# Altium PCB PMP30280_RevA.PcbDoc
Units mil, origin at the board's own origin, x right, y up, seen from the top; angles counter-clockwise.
Board outline 5275 x 1618.75 mil, 2 copper layers (Top Layer, Bottom Layer), stack 62 mil thick; 59 components, 35 nets, 134 pads, 11 vias.
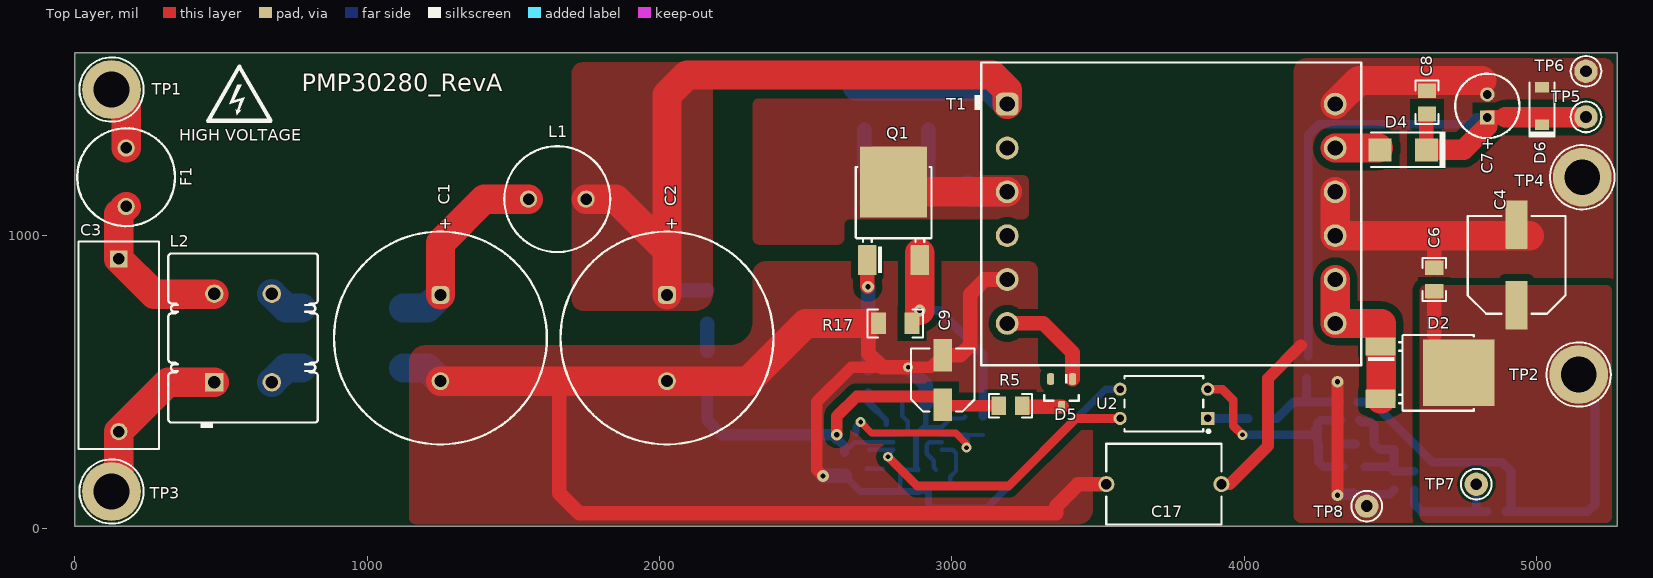
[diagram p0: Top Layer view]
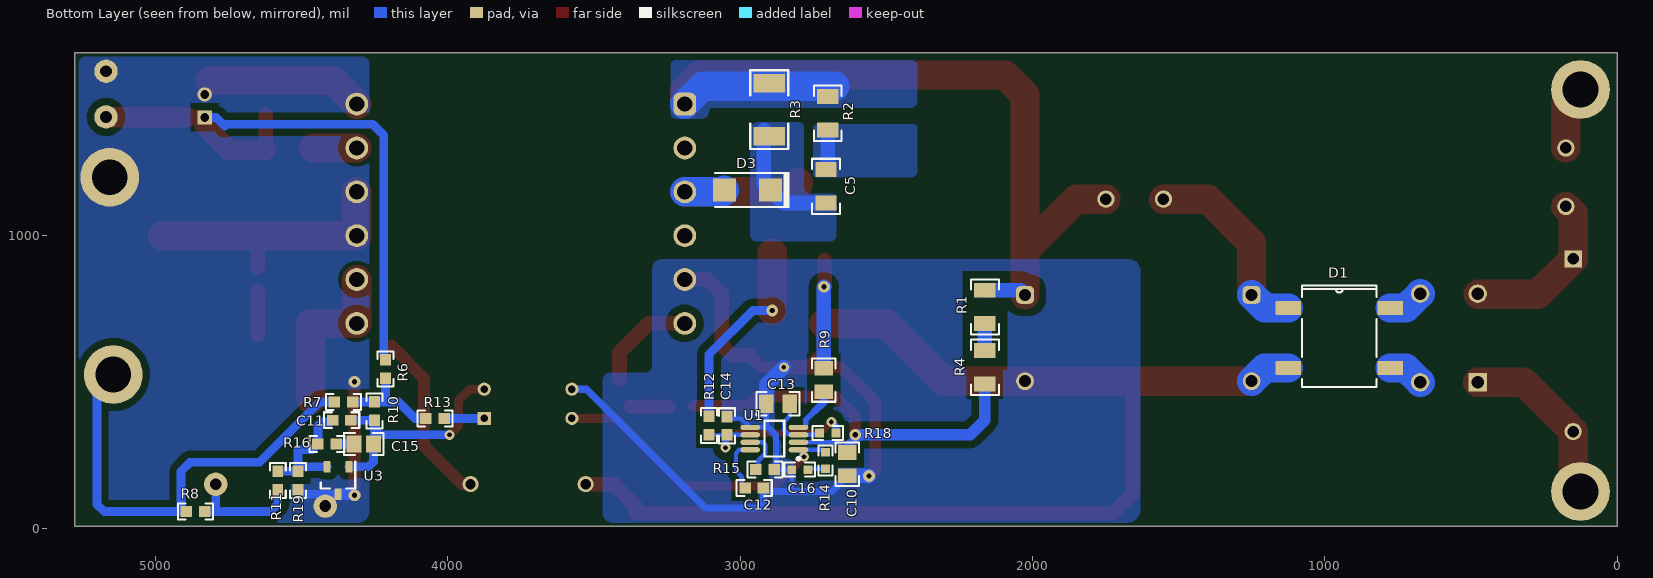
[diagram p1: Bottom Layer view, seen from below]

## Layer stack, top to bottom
Top Solder: solder mask 0.4, Solder Resist, Dk 3.5
Top Layer: signal copper 1.4
Dielectric1: core 59.2, FR-4, Dk 4.8
Bottom Layer: signal copper 1.4
Bottom Solder: solder mask 0.4, Solder Resist, Dk 3.5

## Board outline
0,6.25 5275,6.25 5275,1625 0,1625

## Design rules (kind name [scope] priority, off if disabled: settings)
AcuteAngle [All] p1: minimum=4.50000000000000E+0001 checktracksonly=FALSE
AssemblyTestPointUsage [All] p1: valid=2
Clearance Clearance_PGND_NetR1_1 [InNet('PGND') vs InNet('NetR1_1')] p1: gap=40 ignorepadtopadclearanceinfootprint=FALSE
Clearance Clearance_PGND_NetC2_1 [InNet('PGND') vs InNet('NetC2_1')] p2: gap=40 ignorepadtopadclearanceinfootprint=FALSE
Clearance Clearance_Keepouts [((IsTrack Or IsArc) And Not InPoly) And IsFree and IsKeepOut vs ((IsTrack Or IsArc) And Not InPoly) And IsFree and IsKeepOut] p3: gap=0 ignorepadtopadclearanceinfootprint=FALSE
Clearance Clearance_BoardEdge_MountingHoles [OnCopper and InComponentClass('Mounting Holes') vs IsKeepOut] p4: gap=40 ignorepadtopadclearanceinfootprint=FALSE except(0: Arc-Hole Track-Hole SMDPad-Hole THPad-Hole Via-Hole Fill-Hole Poly-Hole Region-Hole Text-Hole)
Clearance Clearance_BoardEdge_Poly [OnCopper and InPoly vs IsKeepOut] p5: gap=25 ignorepadtopadclearanceinfootprint=FALSE except(0: Arc-Hole Track-Hole SMDPad-Hole THPad-Hole Via-Hole Fill-Hole Poly-Hole Region-Hole Text-Hole)
Clearance Clearance_BoardEdge [OnCopper and Not InComponentClass('Logo') and not InComponentClass('FiducialMark') and not InRegion(1000,500,4000,800) and Not IsKeepout vs IsKeepOut] p6: gap=75 ignorepadtopadclearanceinfootprint=FALSE except(0: Arc-Hole Track-Hole SMDPad-Hole THPad-Hole Via-Hole Fill-Hole Poly-Hole Region-Hole Text-Hole)
Clearance Clearance_Poly [InPolygon] p7: gap=25 ignorepadtopadclearanceinfootprint=FALSE except(0: Arc-Hole Track-Hole SMDPad-Hole THPad-Hole Via-Hole Fill-Hole Poly-Hole Region-Hole Text-Hole)
Clearance [All] p8: gap=7.87 ignorepadtopadclearanceinfootprint=FALSE except(0: Arc-Hole Track-Hole SMDPad-Hole THPad-Hole Via-Hole Fill-Hole Poly-Hole Region-Hole Text-Hole)
ComponentClearance ComponentClearance_MountingHoles_FiducialMarks [InComponentClass('Mounting Holes') vs InComponentClass('FiducialMark')] p1: gap=20 collisioncheckmode=3 verticalgap=10 showdistances=FALSE
ComponentClearance ComponentClearance_Shunt [InComponentClass('Header') vs InComponentClass('Shunt')] p2: gap=0 collisioncheckmode=3 verticalgap=0 showdistances=FALSE
ComponentClearance ComponentClearance_Logo [InComponentClass('Logo')] p3: gap=20 collisioncheckmode=3 verticalgap=10 showdistances=FALSE
ComponentClearance ComponentClearance_ScrewToNut [(HasFootprint('NY PMS 440 0025 PH')) vs (HasFootprint('Keystone_1902C'))] p4: gap=5 collisioncheckmode=3 verticalgap=10 showdistances=FALSE
ComponentClearance ComponentClearance_MountingHoles [InComponentClass('Mounting Holes')] p5: gap=20 collisioncheckmode=3 verticalgap=100000 showdistances=FALSE
ComponentClearance ComponentClearance_SmallPassives [HasFootprint('0201*') or HasFootprint('0402*') or HasFootprint('0508') or HasFootprint('0603*') or HasFootprint('0612') or HasFootprint('0805*') or HasFootprint('0815*') or HasFootprint('0830*') or HasFootprint('1206*') or HasFootprint('1210*') or HasFootprint('1808*') or HasFootprint('1812*') or HasFootprint('1825*') or HasFootprint('2010*') or HasFootprint('2220*') or HasFootprint('2225*') or HasFootprint('2512*') or HasFootprint('2728*') or HasFootprint('3518*') vs HasFootprint('0201*') or HasFootprint('0402*') or HasFootprint('0508') or HasFootprint('0603*') or HasFootprint('0612') or HasFootprint('0805*') or HasFootprint('0815*') or HasFootprint('0830*') or HasFootprint('1206*') or HasFootprint('1210*') or HasFootprint('1808*') or HasFootprint('1812*') or HasFootprint('1825*') or HasFootprint('2010*') or HasFootprint('2220*') or HasFootprint('2225*') or HasFootprint('2512*') or HasFootprint('2728*') or HasFootprint('3518*')] p6: gap=20 collisioncheckmode=3 verticalgap=10 showdistances=FALSE
ComponentClearance ComponentClearance_THtoSMT [IsThruComponent vs IsSMTComponent] p7: gap=20 collisioncheckmode=3 verticalgap=30 showdistances=FALSE
ComponentClearance ComponentClearance_THtoTH [IsThruComponent vs IsThruComponent] p8: gap=20 collisioncheckmode=3 verticalgap=30 showdistances=FALSE
ComponentClearance [All] p9: gap=20 collisioncheckmode=3 verticalgap=10 showdistances=FALSE
DiffPairsRouting [All] p1: maxlimit=100 minlimit=10 mostfreqgap=10 toplayer_minwidth=15 toplayer_maxwidth=15 toplayer_prefwidth=15 bottomlayer_minwidth=15 bottomlayer_maxwidth=15 bottomlayer_prefwidth=15 maxuncoupledlength=1000
FabricationTestPointUsage TestPointUsage [All] p1: valid=2 allowmultiple=FALSE
FabricationTestpoint Testpoint [All] p1: side=3 testpointundercomponent=TRUE minsize=40 maxsize=100 preferedsize=60 minholesize=0 maxholesize=40 preferedholesize=32 testpointgrid=1 allowsidetop=TRUE allowsidebottom=TRUE usegrid=TRUE gridtolerance=0.01
FanoutControl Fanout_LCC [IsLCC] p1: bgadir=Out bgaviamode=Centered fanoutstyle=Auto fanoutdirection=Alternating viagrid=1 // Fanout_LCC (Default Rule)
FanoutControl Fanout_BGA [IsBGA] p2: bgadir=Out bgaviamode=Centered fanoutstyle=Auto fanoutdirection=Alternating viagrid=1 // Fanout_BGA (Default Rule)
FanoutControl Fanout_Default [All] p4: bgadir=Out bgaviamode=Centered fanoutstyle=Auto fanoutdirection=Alternating viagrid=1 // Fanout_Default (Default Rule)
FanoutControl Fanout_Small [(CompPinCount < 5)] p5: bgadir=Out bgaviamode=Centered fanoutstyle=Auto fanoutdirection=OutThenIn viagrid=1 // Fanout_Small (Default Rule)
Height [All] p1: minheight=0 maxheight=1500 prefheight=500
HoleSize [All] p1: absolutevalues=TRUE maxlimit=251 minlimit=8 maxpercent=80.000 minpercent=20.000
MinimumAnnularRing MinimumAnnularRing_ThermalPadVias [IsVia and InAnyComponent] p1: minimumring=5.91
MinimumAnnularRing [All] p2: minimumring=9
MinimumSolderMaskSliver MinimumSolderMaskSliver_Logo [InComponentClass('Logo') vs InComponentClass('Logo')] p1: minsoldermaskwidth=0.7
MinimumSolderMaskSliver [All] p2: minsoldermaskwidth=3.94
PlaneConnect [All] p1: planeconnectstyle=Relief reliefexpansion=10 reliefentries=4 reliefconductorwidth=10 reliefairgap=10
PolygonConnect [All] p1: connectstyle=Direct reliefconductorwidth=10 reliefentries=4 polygonreliefangle="90 Angle" airgapwidth=10
RoutingVias ThermalPadVias [IsVia and InAnyComponent] p1: holewidth=7.87 width=19.68 viastyle="Through Hole" minholewidth=7.87 minwidth=19.68 maxholewidth=12.99 maxwidth=23.62
RoutingVias [All] p2: holewidth=16 width=34 viastyle="Through Hole" minholewidth=7.87 minwidth=26 maxholewidth=40 maxwidth=65
SilkToBoardRegionClearance [Not ((IsComment or IsDesignator) And (Hide <> 'False')) and not InRegion(1000,500,4000,800)] p1:
SilkToSilkClearance SilkToSilkClearance_Pb-FreeLogo [(HasFootprint('Pb-Free_Overlay_Medium') OR HasFootprint('Pb-Free_Overlay_Small')) vs (HasFootprint('Pb-Free_Overlay_Medium') OR HasFootprint('Pb-Free_Overlay_Small'))] p1: silktosilkclearance=0
SilkToSilkClearance [All] p2: silktosilkclearance=0.1
SilkToSolderMaskClearance SilkToComonentPadClearance [IsPad and InAnycomponent] p1: minsilkscreentomaskgap=1 clearancetoexposedcopper=TRUE
SilkToSolderMaskClearance "Silk to Solder Mask Opening" [All] p2: minsilkscreentomaskgap=1 clearancetoexposedcopper=FALSE
SolderMaskExpansion [All] p1: expansion=1.97
Width [All] p1: maxlimit=100 minlimit=6 preferedwidth=10 checkconnectedcopper=TRUE
14 further rules are at their usual default settings.

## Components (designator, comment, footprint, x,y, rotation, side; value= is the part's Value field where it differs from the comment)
C1 "EKXG401ELL101MMN3S" Chemi-Con_1800x3150 1250,650 r270 top value=100uF
C2 "EKXG401ELL101MMN3S" Chemi-Con_1800x3150 2025,650 r270 top value=100uF
C3 "B32922C3224K" B32922_12.5mm 150,625 r270 top value=0.22uF
C4 "875115250001" WCAP-PSHP_800x770 4931.25,900 r90 top value=330uF
C5 "GRM31BR72J152KW01L" 1206 2706.25,1168.75 r270 bottom value=1500pF
C6 "0805ZC105KAT2A" 0805_HV 4650,850 r90 top value=1uF
C7 "EKZN350ELL470ME11D" Chemi-Con_500x1100 4831.25,1443.75 r90 top value=47uF
C8 "GRM21BR71H105KA12L" 0805_HV 4625,1456.25 r90 top value=1uF
C9 "EEE-FC1V6R8R" SM_RADIAL_C 2968.75,506.25 r90 top value=6.8uF
C10 "CC0805KRX7R9BB104" 0805_HV 2632.68,218.45 r270 bottom value=0.1uF
C11 "C0603C681K5RACTU" 0603 4362.5,368.75 r180 bottom value=680pF
C12 "C1608X7R1H473K080AA" 0603 2951.43,137.2 r180 bottom value=0.047uF
C13 "08055C105KAT2A" 0805_HV 2870.18,424.7 r0 bottom value=1uF
C14 "C0603C221K5RACTU" 0603 3045.18,349.7 r90 bottom value=220pF
C15 "Used in BOM report" 0805 4287.5,287.5 r180 bottom value=DNP
C16 "Used in BOM report" 0603_HV 2795.18,199.7 r0 bottom value=DNP
C17 "DE1E3KX222MN4AP01F" KX_1000x700 3725,150 r180 top value=2200pF
D1 "DF04S" DF-S 950,650 r180 bottom value=600V
D2 "MBRD580T4G" DPAK 4600,531.25 r0 top value=60V
D3 "US1J-13-F" SMA 2975,1156.25 r0 bottom value=600V
D4 "SS1200-LTP" SMA 4543.75,1293.75 r180 top value=200V
D5 "BAS21-7-F" SOT-23 3375,462.5 r270 top value=200V
D6 "MMSZ5252B-7-F" SOD-123 5018.75,1443.75 r90 top value=24V
F1 "37211000001" FUSE_372 175,1200 r90 top
"HIGH VOLTAGE" "DANGER HIGH VOLTAGE" IEC_HighVoltage_Small 562.5,1481.25 r0 top (schematic designator "HIGH VOLTAGE1")
L1 "DNP" WE-TI_8075_STU 1650,1125 r0 top value=SHORT
L2 "744822110" WE-CMB_Type_S 575,650 r90 top value=10mH
Q1 "STD9HN65M2" DPAK 2800,1050 r90 top value=650V
R1 "CRCW1206249KFKEA" 1206 2162.5,756.25 r90 bottom value=249k
R2 "CRCW120668R0JNEA" 1206 2700,1418.75 r90 bottom value=68
R3 "CRCW2010100KJNEF" 2010 2900,1431.25 r90 bottom value=100k
R4 "CRCW1206249KFKEA" 1206 2162.5,550 r90 bottom value=249k
R5 "CRCW080510R0FKEA" 0805_HV 3200,418.75 r0 top value=10.0
R6 "CRCW06030000Z0EA" 0603 4212.5,543.75 r90 bottom value=0
R7 "Used in BOM report" 0603 4356.25,431.25 r0 bottom value=DNP
R8 "CRCW060349R9FKEA" 0603 4862.5,56.25 r0 bottom value=49.9
R9 "CRCW08050000Z0EA" 0805_HV 2713.93,505.95 r90 bottom value=0
R10 "Used in BOM report" 0603 4250,400 r90 bottom value=DNP
R11 "CRCW060349K9FKEA" 0603 4581.25,162.5 r270 bottom value=49.9k
R12 "CRCW06031K21FKEA" 0603 3106.25,350.59 r90 bottom value=1.21k
R13 "CRCW06032K00JNEA" 0603 4043.75,375 r0 bottom value=2.0k
R14 "Used in BOM report" 0603_HV 2707.68,230.95 r90 bottom value=DNP
R15 "CRCW060351K1FKEA" 0603 2913.93,199.7 r0 bottom value=51.1k
R16 "Used in BOM report" 0603 4412.5,287.5 r0 bottom value=DNP
R17 "ERJ-8RQFR56V" 1206 2806.25,700 r0 top value=0.56
R18 "Used in BOM report" 0603_HV 2700,325 r0 bottom value=DNP
R19 "CRCW060335K7FKEA" 0603 4512.5,162.5 r90 bottom value=35.7k
T1 "750317021" Wurth_EFD25_6008 3750,1075 r0 top value=2mH
TP1 "Suggest using a net name here" Keystone1503-2 125,1500 r0 top
TP2 "Suggest using a net name here" Keystone1503-2 5143.75,525 r0 top value=Double
TP3 "Suggest using a net name here" Keystone1503-2 125,125 r0 top
TP4 "Suggest using a net name here" Keystone1503-2 5156.25,1200 r0 top value=Double
TP5 "5000" Keystone5000 5168.75,1406.25 r0 top value=Red
TP6 "5001" Keystone5001 5168.75,1562.5 r0 top value=Black
TP7 "5000" Keystone5000 4793.75,150 r90 top value=Red
TP8 "5001" Keystone5001 4418.75,75 r90 top value=Black
U1 "LM5021MM-1/NOPB" MUA08A_N 2882.68,305.95 r0 bottom
U2 "FOD817A" DIP-4 3725,425 r180 top
U3 "ATL431AIDBZR" DBZ0003A_N 4375,162.5 r270 bottom

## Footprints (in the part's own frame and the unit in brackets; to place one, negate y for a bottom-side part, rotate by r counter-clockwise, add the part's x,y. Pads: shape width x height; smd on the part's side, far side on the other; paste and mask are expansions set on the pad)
0603 [mm] "0603 from SM-752 data"
  rect 1x0.95 smd: 1(-0.8,0) 2(0.8,0)
  silkscreen extent -1.52,-0.69 1.52,0.69, body extent -0.87,-0.47 0.87,0.47, height 1
0603_HV [mil] "Ernesto recommended land pattern.  26 mil between pads."
  rect 30x30 smd: 1(-28,0) 2(28,0)
  silkscreen extent -52,-24 52,24, body extent -34,-19 34,19, height 39
0805 [mm] "0805 from SM-752 data"
  rect 1.3x1.5 smd: 1(-0.85,0) 2(0.85,0)
  silkscreen extent -1.72,-0.97 1.72,0.97, body extent -1.1,-0.72 1.1,0.72, height 1.45
0805_HV [mil] "0805 with 30mil clearance between pads"
  rect 50x63 smd: 1(-40,0) 2(40,0)
  silkscreen extent -74,-40 74,40, body extent -43,-29 43,29, height 57
1206 [mm] "1206 from SM-752 data"
  rect 1.3x1.85 smd: 1(-1.45,0) 2(1.45,0)
  silkscreen extent -2.4,-1.21 2.4,1.21, body extent -1.7,-0.9 1.7,0.9, height 1.35
2010 [mm] "Chip Capacitor, Body 5.08x2.54mm, IPC Medium Density"
  rect 1.6x2.7 smd: 1(-2.3,0) 2(2.3,0)
  silkscreen extent -3.42,-1.65 3.42,1.65, body extent -2.73,-1.45 2.73,1.45, height 1.66
B32922_12.5mm [mm] "Epcos film capacitors, 15mm spacing"
  rect 1.5x1.5 hole 1: 1(-7.5,0)
  round 1.5 hole 1: 2(7.5,0)
  silkscreen extent -9,-3.5 9,3.5, body extent -9,-3.5 9,3.5, height 12.5
Chemi-Con_500x1100 [mm] "TH, 2-Leads, Dia 5mm, Lead Sapcing 2mm"
  rect 1.25x1.25 hole 0.75: 1(-1,0)
  round 1.25 hole 0.75: 2(1,0)
  silkscreen extent -2.8,-2.8 2.8,2.8, body extent -2.75,-2.75 2.75,2.75, height 12.5
Chemi-Con_1800x3150 [mm] "TH, 2-Leads, Dia 18mm, Pin Spacing 7.5mm"
  rrect50% 1.55x1.55 hole 1.05: 1(-3.75,0)
  round 1.55 hole 1.05: 2(3.75,0)
  silkscreen extent -9.25,-9.25 9.25,9.25, body extent -9.25,-9.35 9.26,9.15, height 33.01
DBZ0003A_N [mm] "SOT23, 3-Leads, Body 2.9x1.3mm, Pitch 0.95mm, Lead Span 2.4mm, IPC Medium Density"
  rrect17% 1x0.6 smd: 1(-1.2,0.95) 2(-1.2,-0.95) 3(1.2,0)
  silkscreen extent -1.65,-1.5 0.7,1.5, body extent -1.26,-1.46 1.26,1.46, height 0.98
DF-S [mil] "Diodes Inc. recommended land pattern per ap02001.pdf rev 30"
  rect 88x49 smd: 1(-174.5,102.36) 2(-174.5,-102.36) 3(174.5,-102.36) 4(174.5,102.36)
  silkscreen extent -128,-168 128,180, body extent -205,-168 205,168, height 108
DIP-4 [mm] "DIP, 4-Leads, Body 6.86x4.83mm, Pitch 2.54mm"
  rect 1.15x1.15 hole 0.65: 1(-3.81,1.27)
  round 1.15 hole 0.65: 2(-3.81,-1.27) 3(3.81,-1.27) 4(3.81,1.27)
  silkscreen extent -4,-2.41 3.43,2.52, body extent -4.02,-2.41 4.02,2.41, height 5.59
DPAK [mm] "D-PAK, 3-Pads, Body 6.22x6.73mm (max), TO-252AA using nominal STEP model"
  rrect6% 2.6x1.6 smd: 1(-3.4,2.28) 3(-3.4,-2.28)
  rrect2% 6.2x5.8 smd paste-2.9: 4(3.4,0)
  silkscreen extent -4.5,-3.3 4.7,3.28, body extent -3.86,-3.29 5.84,3.29, height 2.48
FUSE_372 [mm] "LITTELFUSE"
  round 1.5 hole 1: 1(-2.54,0) 2(2.54,0)
  silkscreen extent -4.25,-4.25 4.25,4.25, body extent -4.25,-4.25 4.25,4.25, height 8
IEC_HighVoltage_Small [mil]
  silkscreen extent -107,-88 107,97
Keystone1503-2 [mm] "Double Turret"
  round 5.1 hole 3.1: 1(0,0)
  silkscreen extent -2.79,-2.79 2.79,2.79, body extent -2.4,-2.4 2.38,2.4, height 9.22
Keystone5000 [mil] "For Keystone 500x miniature loop terminals"
  round 80 hole 40: 1(0,0)
  silkscreen extent -52,-52 52,52, body extent -49,-49 49,49, height 182
Keystone5001 [mil] "For Keystone 500x miniature loop terminals"
  round 80 hole 40: 1(0,0)
  silkscreen extent -52,-52 52,52, body extent -49,-49 49,49, height 182
KX_1000x700 [mm] "TH, 2-Leads, Dia 10mm, Lead Spacing 10mm"
  round 1.4 hole 0.9: 1(-5,0) 2(5,0)
  silkscreen extent -5,-3.5 5,3.5, body extent -5.32,-3.5 5.33,3.5, height 12.99
MUA08A_N [mm] "TSOP, 8-Leads, Body 3x3mm, Pitch 0.65mm, IPC Medium Density"
  oval 1.7x0.45 smd: 1(-2.1,0.975) 2(-2.1,0.325) 3(-2.1,-0.325) 4(-2.1,-0.975) 5(2.1,-0.975) 6(2.1,-0.325) 7(2.1,0.325) 8(2.1,0.975)
  silkscreen extent -2.22,-1.55 0.85,1.87, body extent -1.6,-1.6 1.6,1.6, height 1.09
SM_RADIAL_C [mm] "5 x 5.8mm:  Panasonic C"
  rect 2.8x1.6 smd: 1(-2.15,0) 2(2.15,0)
  silkscreen extent -2.75,-2.75 2.75,2.75, body extent -2.75,-2.75 2.75,2.75, height 6.1
SMA [mm] "Molded Diode, 2-Leads, Body 4.3x2.6mm, IPC Medium Density, based on OnSemi component dimensions and land pattern"
  rect 2x2 smd: 1(-2,0) 2(2,0)
  silkscreen extent -3.66,-1.57 2.79,1.57, body extent -2.6,-1.3 2.6,1.3, height 2.42
SOD-123 [mm] "On Semi recommended land pattern"
  rect 0.915x1.22 smd: 1(-1.637,0) 2(1.637,0)
  silkscreen extent -2.74,-1.17 2.03,1.17, body extent -1.93,-0.9 1.93,0.9, height 1.35
SOT-23 [mm] "SOT23, 3-Leads, Body 2.9x1.3mm, Pitch 0.95mm, Lead Span 2.5mm, IPC Medium Density"
  rrect50% 1x0.6 smd: 1(-1.2,0.95) 2(-1.2,-0.95) 3(1.2,0)
  silkscreen extent -1.63,-1.5 0.7,1.5, body extent -1.16,-1.45 1.21,1.45, height 1
WCAP-PSHP_800x770 [mm] "SMD, 2-Leads, Body 8.3x8.3mm"
  rrect5% 4.2x1.9 smd: 1(-3.5,0) 2(3.5,0)
  silkscreen extent -4.25,-4.25 4.25,4.25, body extent -4.5,-4.15 4.5,4.15, height 7.67
WE-CMB_Type_S [mm] "TH, 4-Leads, Body 14.7x13mm"
  rect 1.6x1.6 hole 1.1: 1(-3.85,2.5)
  round 1.6 hole 1.1: 2(-3.85,-2.5) 3(3.85,-2.5) 4(3.85,2.5)
  silkscreen extent -7.8,-6.5 7.35,6.5, body extent -7.77,-6.5 7.77,6.5, height 20
WE-TI_8075_STU [mm] "TH, 2-Leads, Dia 9.5mm, Pin Spacing 5mm"
  round 1.5 hole 1: 1(-2.5,0) 2(2.5,0)
  silkscreen extent -4.6,-4.6 4.6,4.6, body extent -5.8,-5.8 5.8,5.8, height 9.7
Wurth_EFD25_6008 [mm] "TH, 12-Leads, Body 33x26.3mm"
  rrect50% 1.98x1.98 hole 1.32: 1(-14.25,9.525)
  round 1.98 hole 1.32: 2(-14.25,5.715) 3(-14.25,1.905) 4(-14.25,-1.905) 5(-14.25,-5.715) 6(-14.25,-9.525) 7(14.25,-9.525) 8(14.25,-5.715) 9(14.25,-1.905) 10(14.25,1.905) 11(14.25,5.715) 12(14.25,9.525)
  silkscreen extent -17.1,-13.15 16.5,13.15, body extent -16.01,-12.98 16,12.99, height 13.95

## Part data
C1 C2: library part CMP-0074694-1, "CAP, AL, 100 µF, 400 V, +/- 20%, TH", Cap_Case=18x31.5, Manufacturer=Chemi-Con, Supplier Part Number 1=565-1469-ND, Tolerance_%=20%, Value2=400V, ValueDisplayed=100µF
C3: "CAP, Film, 0.22 µF, 630 V,+/- 10%, TH", Manufacturer=TDK, Supplier Part Number 1=495-6907-ND, Tolerance_%=10, Value2=630V, ValueDisplayed=0.22µF
C4: library part CMP-0001609-3, "CAP, Aluminum Polymer, 330 µF, 10 V,+/- 20%, 0.02 ohm, D8xL7.7mm SMD", Cap_Case=8X7.7mm, Manufacturer="Wurth Elektronik", Supplier Part Number 1=732-6449-1-ND, Tolerance_%=20%, Value1="0.02 ohm", Value2=10V, ValueDisplayed=330µF
C5: "CAP, CERM, 1500 pF, 630 V,+/- 10%, X7R, 1206", Cap_Case=1206, Manufacturer=MuRata, Supplier Part Number 1=490-3507-1-ND, TempCo=X7R, Tolerance_%=10, Value2=630V, ValueDisplayed=1500pF
C6: "CAP, CERM, 1 µF, 10 V,+/- 10%, X7R, 0805", Cap_Case=0805, Manufacturer=AVX, Supplier Part Number 1=478-1405-1-ND, TempCo=X7R, Tolerance_%=10, Value1="0.008 ohm", Value2=10V, ValueDisplayed=1µF
C7: library part CMP-0074695-1, "CAP, AL, 47 µF, 35 V, +/- 20%, 0.38 ohm, TH", Cap_Case=5x11, Manufacturer=Chemi-Con, Supplier Part Number 1=565-4239-ND, Tolerance_%=20%, Value1="0.38 ohm", Value2=35V, ValueDisplayed=47µF
C8: "CAP, CERM, 1 µF, 50 V,+/- 10%, X7R, 0805", Cap_Case=0805, Manufacturer=MuRata, Supplier Part Number 1=490-4736-1-ND, TempCo=X7R, Tolerance_%=10, Value1=Unknown, Value2=50V, ValueDisplayed=1µF
C9: "CAP, AL, 6.8 µF, 35 V, +/- 20%, 1.8 ohm, SMD", Cap_Case=C, Manufacturer=Panasonic, Supplier Part Number 1=PCE4033CT-ND, Tolerance_%=20, Value1="1.8 ohm", Value2=35V, ValueDisplayed=6.8µF
C10: "CAP, CERM, 0.1 µF, 50 V,+/- 10%, X7R, 0805", Cap_Case=0805, Manufacturer="Yageo America", Supplier Part Number 1=311-1140-1-ND, TempCo=X7R, Tolerance_%=10, Value2=50V, ValueDisplayed=0.1µF
C11: "CAP, CERM, 680 pF, 50 V, +/- 10%, X7R, 0603", Cap_Case=0603, Manufacturer=Kemet, Supplier Part Number 1=399-1077-1-ND, TempCo=X7R, Tolerance_%=10, Value1=Unknown, Value2=50V, ValueDisplayed=680pF
C12: "CAP, CERM, 0.047 µF, 50 V,+/- 10%, X7R, 0603", Cap_Case=0603, Manufacturer=TDK, Supplier Part Number 1=445-1313-1-ND, TempCo=X7R, Tolerance_%=10, Value1="0.049007 ohm", Value2=50V, ValueDisplayed=0.047µF
C13: "CAP, CERM, 1 µF, 50 V, +/- 10%, X7R, 0805", Cap_Case=0805, Manufacturer=AVX, Supplier Part Number 1=478-7956-1-ND, TempCo=X7R, Tolerance_%=10, Value1=Unknown, Value2=50V, ValueDisplayed=1µF
C14: "CAP, CERM, 220 pF, 50 V,+/- 10%, X7R, 0603", Cap_Case=0603, Manufacturer=Kemet, Supplier Part Number 1=399-1071-1-ND, TempCo=X7R, Tolerance_%=10, Value1=Unknown, Value2=50V, ValueDisplayed=220pF
C15 C16: library part Capacitor, "CAP, CERM, xxxF, xxV, [TempCo], xx%, [PackageReference]", Alternate Manufacturer=-
C17: library part DE1E3KX332MN4AP01F, "CAP, CERM, 2200 pF, 300 V, +/- 20%, E, D10xT7mm", Cap_Case=10x7mm, Manufacturer=MuRata, Supplier Part Number 1=490-9516-1-ND, TempCo=E, Tolerance_%=20, Value1=Unknown, Value2=300V, ValueDisplayed=2200pF
D1: library part DF06S-E3, "Diode, Switching-Bridge, 400 V, 1.5A,", Current - Reverse Leakage @ Vr="5µA @ 400V", Manufacturer=Vishay-Semiconductor, Operating Temperature="-55°C ~ 150°C (TJ)", Supplier Device Package=4-SDIP, Supplier Part Number 1=DF04S-E3/45GI-ND, Value1=1A, Value2=1.1V, Voltage - Peak Reverse (Max)=400V
D2: library part MBRD360T4G, "Diode, Schottky, 80 V, DPAK", Capacitance @ Vr, F="300pF @ 5V, 1MHz", Current - Reverse Leakage @ Vr="1mA @ 80V", Manufacturer="SMC Diode Solutions", Operating Temperature - Junction="-55°C ~ 150°C", Supplier Device Package=DPAK, Supplier Part Number 1=MBRD580, Value1=3A, Value2=0.6V
D3: "Diode, Ultrafast, 600 V, 1 A, SMA", Manufacturer="Diodes Inc.", Supplier Part Number 1=US1J-FDICT-ND, Value1=1A, Value2=1.7V
D4: "Diode, Schottky, 200 V, 1 A, SMA", Manufacturer="Micro Commercial Components", Supplier Part Number 1=SS1200-LTPMSCT-ND, Value1=1A, Value2=0.92V
D5: "Diode, Switching, 200 V, 0.2 A, SOT-23", Manufacturer="Diodes Inc.", Supplier Part Number 1=BAS21-FDICT-ND, Value1=0.2A, Value2=1.25V
D6: "Diode, Zener, 24 V, 500 mW, SOD-123", Manufacturer="Diodes Inc.", Power_W=0.5, Supplier Part Number 1=MMSZ5252B-FDICT-ND, Value1=0.5W
F1: "Fuse, 1 A, 250VAC/VDC, TH", Irating_A=1, Manufacturer=Littelfuse, Supplier Part Number 1=WK4248CT-ND
"HIGH VOLTAGE": library part IEC_HighVoltage, "IEC 61010-1 High Voltage Warning"
L1: library part 744732681, "Inductor, Unshielded Drum Core, Metal Composite, 680 µH, 0.42 A, 2.2 ohm, TH", Manufacturer="Wurth Elektronik", Supplier Part Number 1=732-3753-ND, Value1="2.2 ohm", Value2=0.42A, ValueDisplayed=SHORT
L2: "Coupled inductor, 10 mH, 1 A, 0.36 ohm, TH", Manufacturer="Wurth Elektronik", Supplier Part Number 1=732-1442-ND, ValueDisplayed=10mH
Q1: library part CMP-0001614-1, "MOSFET, N-CH, 650 V, 5.5 A, DPAK", Alternate Manufacturer=None, Manufacturer=STMicroelectronics, Supplier Part Number 1=497-16036-1-ND, Value1="? ohm", Value2="11.5 nC"
R1 R4: "RES, 249 k, 1%, 0.25 W, 1206", Manufacturer=Vishay-Dale, Power_W=0.25, Supplier Part Number 1=541-249KFCT-ND, TempCo="100 ppm/C", Tolerance_%=1, Value1=1%, Value2=0.25W, Value_Code=249k
R2: "RES, 68, 5%, 0.25 W, 1206", Manufacturer=Vishay-Dale, Power_W=0.25, Supplier Part Number 1=541-68ECT-ND, TempCo="200 ppm/C", Tolerance_%=5, Value1=5%, Value2=0.25W, Value_Code=68R0, ValueDisplayed=68
R3: "RES, 100 k, 5%, 0.75 W, AEC-Q200 Grade 0, 2010", Manufacturer=Vishay-Dale, Power_W=0.75, Supplier Part Number 1=541-100KWCT-ND, TempCo="200 ppm/C", Tolerance_%=5, Value1=5%, Value2=0.75W, Value_Code=100k
R5: "RES, 10.0, 1%, 0.125 W, 0805", Manufacturer=Vishay-Dale, Power_W=0.125, Supplier Part Number 1=541-10.0CCT-ND, TempCo="100 ppm/C", Tolerance_%=1, Value1=1%, Value2=0.125W, Value_Code=10R0, ValueDisplayed=10.0
R6: "RES, 0, 5%, 0.1 W, 0603", Manufacturer=Vishay-Dale, Power_W=0.1, Supplier Part Number 1=541-0.0GCT-ND, TempCo="200 ppm/C", Tolerance_%=5, Value1=5%, Value2=0.1W, Value_Code=0000, ValueDisplayed=0
R7 R10 R14 R16 R18: library part Resistor, "RES, xxx ohm, x%, xW, [PackageReference]", Alternate Manufacturer=-
R8: "RES, 49.9, 1%, 0.1 W, 0603", Manufacturer=Vishay-Dale, Power_W=0.1, Supplier Part Number 1=541-49.9HCT-ND, TempCo="100 ppm/C", Tolerance_%=1, Value1=1%, Value2=0.1W, Value_Code=49R9, ValueDisplayed=49.9
R9: "RES, 0, 5%, 0.125 W, 0805", Manufacturer=Vishay-Dale, Power_W=0.125, Supplier Part Number 1=541-0.0ACT-ND, TempCo="200 ppm/C", Tolerance_%=5, Value1=5%, Value2=0.125W, Value_Code=0000, ValueDisplayed=0
R11: "RES, 49.9 k, 1%, 0.1 W, 0603", Manufacturer=Vishay-Dale, Power_W=0.1, Supplier Part Number 1=541-49.9KHCT-ND, TempCo="100 ppm/C", Tolerance_%=1, Value1=1%, Value2=0.1W, Value_Code=49k9, ValueDisplayed=49.9k
R12: "RES, 1.21 k, 1%, 0.1 W, 0603", Manufacturer=Vishay-Dale, Power_W=0.1, Supplier Part Number 1=541-1.21KHCT-ND, TempCo="100 ppm/C", Tolerance_%=1, Value1=1%, Value2=0.1W, Value_Code=1k21, ValueDisplayed=1.21k
R13: "RES, 2.0 k, 5%, 0.1 W, 0603", Manufacturer=Vishay-Dale, Power_W=0.1, Supplier Part Number 1=541-2.0KGCT-ND, TempCo="200 ppm/C", Tolerance_%=5, Value1=5%, Value2=0.1W, Value_Code=2k00, ValueDisplayed=2.0k
R15: "RES, 51.1 k, 1%, 0.1 W, 0603", Manufacturer=Vishay-Dale, Power_W=0.1, Supplier Part Number 1=541-51.1KHCT-ND, TempCo="100 ppm/C", Tolerance_%=1, Value1=1%, Value2=0.1W, Value_Code=51k1, ValueDisplayed=51.1k
R17: "RES, 0.56, 1%, 0.25 W, 1206", Manufacturer=Panasonic, Power_W=0.25, Supplier Part Number 1=P.56RCT-ND, TempCo="250 ppm/C", Tolerance_%=1, Value1=1%, Value2=0.25W, Value_Code=R560, ValueDisplayed=0.56
R19: "RES, 35.7 k, 1%, 0.1 W, 0603", Manufacturer=Vishay-Dale, Power_W=0.1, Supplier Part Number 1=541-35.7KHCT-ND, TempCo="100 ppm/C", Tolerance_%=1, Value1=1%, Value2=0.1W, Value_Code=35k7, ValueDisplayed=35.7k
T1: library part CMP-0077154-2, "Transformer, 2000 uH, TH", Manufacturer="Wurth Elektronik", ValueDisplayed=2mH
TP1 TP3: library part 1503-2, "Terminal, Turret, TH, Double", Manufacturer=Keystone, Supplier Part Number 1=36-1503-2-ND
TP2 TP4: library part 1503-2, "Terminal, Turret, TH, Double", Manufacturer=Keystone, Supplier Part Number 1=1503-2K-ND
TP5 TP7: "Test Point, Miniature, Red, TH", Manufacturer=Keystone, Supplier Part Number 1=5000K-ND
TP6 TP8: "Test Point, Miniature, Black, TH", Manufacturer=Keystone, Supplier Part Number 1=5001K-ND
U1: "AC-DC Current Mode PWM Controller, 8-pin MSOP, Pb-Free", Manufacturer="Texas Instruments", PackageTopMarking=ZXTT*21-1, PowerWise=N, Supplier Part Number 1=LM5021MM-1TR-ND
U2: "Optocoupler, 5 kV, 80-160% CTR, TH", Manufacturer="Fairchild Semiconductor", Supplier Part Number 1=FOD817A-ND, Voltage_Isolation_Vrms=5000V
U3: "2.5V Low Iq Adjustable Precision Shunt Regulator, DBZ0003A (SOT-23-3)", Alternate Manufacturer="Texas Instruments"

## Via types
v1: diameter 40, hole 18, Top Layer to Bottom Layer, 6 vias
v2: diameter 34, hole 16, Top Layer to Bottom Layer, 5 vias

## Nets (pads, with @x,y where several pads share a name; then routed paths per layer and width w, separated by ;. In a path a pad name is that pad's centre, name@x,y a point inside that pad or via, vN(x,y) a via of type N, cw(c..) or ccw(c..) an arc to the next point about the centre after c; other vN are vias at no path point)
6Vout: C4.1 C6.1 D2.4 R7.2 R8.2 TP2.1 | length 1684.2
  Top Layer w50: 4650,658.86 C6.1
  Bottom Layer w30: R7.2 4437.5,431.25 4643.75,225 4881.25,225 4912.5,193.75 4912.5,150 R8.2@4912.5,67.27 ; R8.2 5175,56.25 5200,81.25 5200,468.75 TP2.1
GND: C4.2 C6.2 C7.2 C8.2 C17.1 D6.2 R19.1 T1.9 T1.10 T1.12 TP4.1 TP6.1 TP8.1 U3.3 | length 2652.9
  Top Layer w40: C17.1 3950,150 4081.25,281.25 4081.25,512.5 4193.75,625 ; v1(4318.75,112.5) v1(4318.75,500)
  Top Layer w50: C6.2 4650,1000
  Top Layer w100: T1.10 T1.9 4650,1000 4975.3,1000 ; T1.12 4392.27,1531.25 4812.5,1531.25
  Bottom Layer w30: U3.3 4496.75,115.26 R19.1
  Bottom Layer w40: v1(4318.75,112.5) cw(c4321.51,112.5) 4321.51,115.26 U3.3
NetC1_1: C1.1 D1.1 L1.1 | length 685.3
  Top Layer w100: C1.1 1250,975 1400,1125 L1.1
  Bottom Layer w100: D1.1 1204.72,752.36 C1.1
NetC2_1: C2.1 L1.2 R1.2 R2.2 R3.2 T1.1 | length 2978.3
  Top Layer w100: L1.2 1850,1125 2025,950 ; C2.1 2025,950 ; T1.1 3188.98,1498.52 3137.5,1550 2093.75,1550 2025,1481.25 2025,950
  Bottom Layer w50: C2.1 2040.7,813.34 R1.2
  Bottom Layer w100: 2675,1511.27 3127.71,1511.27 T1.1
NetC3_1: C3.1 F1.1 L2.4 | length 564.9
  Top Layer w100: F1.1 150,1075 C3.1 270.28,800 L2.4@475,800
NetC3_2: C3.2 L2.1 TP3.1 | length 576.2
  Top Layer w100: TP3.1@150,150 C3.2 318.7,498.43 L2.1
NetC5_1: C5.1 R2.1 | length 129.6
  Bottom Layer w50: C5.1@2700,1232.09 R2.1
NetC5_2: C5.2 D3.1 R3.1 | length 391.4
  Bottom Layer w50: C5.2 2851.67,1111.66 D3.1 ; D3.1@2918.75,1178.74 R3.1@2918.75,1361.66
NetC7_1: C7.1 C8.1 D4.1 D6.1 R6.2 TP5.1 | length 2103.1
  Top Layer w50: D4.1 C8.1@4622.49,1413.74 ; C7.1 4891.88,1404.38
  Top Layer w70: D4.1 4750,1293.75 4831.25,1375 ; 4891.88,1404.38 5166.88,1404.38 TP5.1
  Bottom Layer w30: R6.2@4218.75,587.75 4218.75,1343.75 4256.25,1381.25 4768.75,1381.25 ; 4762.5,1375 4768.75,1381.25 ; C7.1 4791.88,1404.38 4768.75,1381.25
NetC9_1: C9.1 C10.1 R4.1 R5.1 U1.2 | length 1488.5
  Top Layer w40: v1(2606.25,318.75) 2606.25,382.32 2673.93,450 2940.35,450 C9.1 ; C9.1@2971.6,418.75 R5.1
  Bottom Layer w15: C10.1 2667.38,293.16 U1.2
  Bottom Layer w30: v1@2606.25,306.25 2632.68,279.82 C10.1
  Bottom Layer w40: R4.1 2162.5,368.75 2212.5,318.75 2593.75,318.75 v1@2606.25,306.25
NetC11_1: C11.1 R11.1 R16.2 R19.2 U3.2 | length 433.4
  Bottom Layer w30: C11.1 4400.25,362.5 4431.25,362.5 4444,349.75 R16.2 4462.99,268.5 4512.5,268.5 R19.2 R11.1 ; U3.2 R19.2@4506.01,209.74
NetC11_2: C11.2 C15.2 R10.1 U2.2 U3.1 | length 808.6
  Top Layer w30: U2.2 3925,475 3962.5,437.5 3962.5,350 v2(3993.75,318.75)
  Bottom Layer w30: v2(3993.75,318.75) 4247.29,318.75 C15.2@4250,316.04 ; 4243.75,337.5 4250,331.25 ; C11.2 4262.5,368.75 4250,356.25 4250,331.25 ; U3.1 4271.51,209.74 4254.04,227.21 C15.2 4250,291.54 C15.2@4250,316.04 ; C15.2@4250,316.04 4250,331.25
NetC12_1: C12.1 U1.8 | length 185
  Bottom Layer w15: U1.8 3002.31,267.57 3013.93,255.95 3013.93,195.18 2993.75,175 2993.75,148.03 C12.1
NetC13_1: C13.1 R18.2 U1.3 | length 228
  Bottom Layer w15: R18.2 2734.25,318.75 U1.3 2801.36,320.11 2834.64,320.11 2848.84,334.3 2848.84,364.39 2830.18,383.05 C13.1
NetC14_1: C14.1 R12.1 R18.1 U1.6 | length 628.6
  Top Layer w25: v2(2687.5,362.5) 2725,325 3012.5,325 3050,287.5 v2(3050,275)
  Bottom Layer w15: U1.6 3044.64,318.75 C14.1 R12.1@3105.36,318.21
  Bottom Layer w25: R18.1 2672,347 v2(2687.5,362.5) ; v2(3050,275) C14.1@3050,313.39
NetC15_1: C15.1 R16.1 | length 60
  Bottom Layer w30: C15.1 R16.1
NetC16_1: C16.1 R14.1 | length 56.2
  Bottom Layer w15: R14.1 C16.1@2763.93,202.95
NetD1_3: D1.3 L2.2 | length 122.5
  Bottom Layer w100: L2.2 722.64,547.64 D1.3
NetD1_4: D1.4 L2.3 | length 122.5
  Bottom Layer w100: L2.3 722.64,752.36 D1.4
NetD2_1: D2.1 D2.3 T1.7 T1.8 | length 567.7
  Top Layer w100: T1.8 T1.7 4468.75,700 4468.75,444.09 cw(c4466.14,444.09) D2.3
NetD3_2: D3.2 Q1.4 T1.3 | length 547.1
  Top Layer w100: Q1.4 ccw(c2833.86,1183.86) 2833.86,1150 T1.3
  Bottom Layer w100: D3.2 ccw(c3059.99,1156.25) 3059.99,1150 T1.3
NetD4_2: D4.2 T1.11 | length 147.7
  Top Layer w100: T1.11 D4.2@4458.76,1300
NetD5_1: D5.1 T1.6 | length 355.2
  Top Layer w50: T1.6 3312.5,700 3412.4,600.1 D5.1
NetD5_3: D5.3 R5.2 | length 131.5
  Top Layer w50: R5.2@3243.49,415.26 D5.3
NetF1_2: F1.2 TP1.1 | length 150
  Top Layer w100: F1.2 TP1.1@175,1450
NetQ1_1: Q1.1 R9.2 | length 371.7
  Top Layer w50: Q1.1 2710.24,827.26 v1(2712.5,825)
  Bottom Layer w50: v1(2712.5,825) 2713.93,823.57 R9.2
NetQ1_3: Q1.3 R12.2 R17.2 | length 688
  Top Layer w100: v1(2889.76,743.75) Q1.3 Q1.3@2889.76,941.14
  Bottom Layer w30: v1(2889.76,743.75) 2956.84,743.75 3106.25,594.34 R12.2
NetR1_1: R1.1 R4.2 | length 92.1
  Bottom Layer w50: R4.2 R1.1
NetR6_1: R6.1 R7.1 R10.2 R13.2 | length 350.4
  Bottom Layer w30: R13.2 4112.5,375 4169,431.5 R10.2 R7.1@4324.51,431.5 ; 4212.5,434.5 R6.1
NetR8_1: R8.1 R11.2 TP7.1 | length 397.4
  Bottom Layer w30: R11.2 4581.25,81.25 4606.25,56.25 R8.1 ; 4793.75,62.5 TP7.1
NetR9_1: R9.1 U1.4 | length 135
  Bottom Layer w20: 2744.34,400 2775,369.34 2775,356.25
  Bottom Layer w25: R9.1 2713.93,430.41 2744.34,400
NetR13_1: R13.1 U2.1 | length 137.3
  Bottom Layer w30: U2.1 R13.1
NetR14_2: R14.2 U1.1 U2.4 | length 1046.3
  Top Layer w30: v2(2781.25,243.75) 2881.25,143.75 3193.75,143.75 3425,375 U2.4
  Bottom Layer w15: R14.2@2716.29,267.57 U1.1 2781.25,248.82 v2(2781.25,243.75)
NetR15_2: R15.2 U1.7 | length 153.1
  Bottom Layer w15: R15.2 2937.5,207.63 2937.5,230.46 2913.93,254.04 2913.93,284.99 2922.1,293.16 U1.7
PGND: C1.2 C2.2 C9.2 C10.2 C12.2 C13.2 C14.2 C16.2 C17.2 D1.2 R15.1 R17.1 T1.5 U1.5 U2.3 | length 7314.9
  Top Layer w40: v1(2559.05,177.8) 2537.5,199.34 2537.5,431.25 2656.25,550 2762.5,550 ; v2(2850,550) 2927.85,550 C9.2
  Top Layer w50: 1656.25,502.36 1656.25,118.75 1725,50 3356.25,50 3356.25,75 3431.25,150 C17.2 ; 2713.93,700 2713.93,598.57 2762.5,550 v2(2850,550) ; C9.2 3028.4,590.9 3062.5,625 3062.5,800 3112.5,850 T1.5
  Top Layer w100: C1.2 1656.25,502.36 C2.2 2302.36,502.36 2500,700 2713.93,700
  Bottom Layer w15: 2823.18,126.53 C16.2 R15.1 ; 2888.93,124.7 C12.2@2907.43,124.7 ; 2902.31,344.34 U1.5 2995.72,374.7 3038.68,374.7 C14.2
  Bottom Layer w20: R15.1 2876.43,205.71 2876.43,318.45 2902.31,344.34 ; 2910.18,358.57 C13.2
  Bottom Layer w25: C10.2 2686.43,124.7 2888.93,124.7 ; C12.2 2919.93,73.82 2925,68.75 3118.75,68.75 3525,475 U2.3
  Bottom Layer w50: v1(2559.05,177.8) 2559.05,178.45 C10.2 ; v2(2850,550) 2910.18,489.82 C13.2
  Bottom Layer w100: D1.2 1204.72,547.64 C1.2
pads on no net: D5.2 T1.2 T1.4

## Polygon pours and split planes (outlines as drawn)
NetD3_2 on Top Layer "Top Layer-No Net" (solid, pour order 30): 2650,1056.25 ccw(c2650,1037.5) 2631.25,1037.5 2631.25,993.75 cw(c2606.25,993.75) 2606.25,968.75 2343.75,968.75 cw(c2343.75,993.75) 2318.75,993.75 2318.75,1450 cw(c2337.5,1450) 2337.5,1468.75 3068.75,1468.75 cw(c3068.75,1443.75) 3093.75,1443.75 3093.75,1225 ccw(c3112.5,1225) 3112.5,1206.25 3243.75,1206.25 cw(c3243.75,1187.5) 3262.5,1187.5 3262.5,1075 cw(c3243.75,1075) 3243.75,1056.25
NetC2_1 on Top Layer "Top Layer-No Net 3" (solid, pour order 26): 1700,781.25 ccw(c1737.5,781.25) 1737.5,743.75 2125,743.75 ccw(c2125,800) 2181.25,800 2181.25,1562.5 ccw(c2150,1562.5) 2150,1593.75 1737.5,1593.75 ccw(c1737.5,1556.25) 1700,1556.25
PGND on Top Layer "Top Layer-No Net 4" (solid, remove dead copper, pour order 22): 1168.75,12.5 cw(c1168.75,37.5) 1143.75,37.5 1143.75,568.75 cw(c1200,568.75) 1200,625 2237.5,625 ccw(c2237.5,706.25) 2318.75,706.25 2318.75,868.75 cw(c2362.5,868.75) 2362.5,912.5 3262.5,912.5 cw(c3262.5,881.25) 3293.75,881.25 3293.75,568.75 ccw(c3337.5,568.75) 3337.5,525 3450,525 cw(c3450,493.75) 3481.25,493.75 3481.25,62.5 cw(c3431.25,62.5) 3431.25,12.5
GND on Top Layer "Top Layer-No Net 2" (solid, remove dead copper, pour order 6): 5256.25,43.75 cw(c5231.25,43.75) 5231.25,18.75 4193.75,18.75 cw(c4193.75,43.75) 4168.75,43.75 4168.75,1562.5 cw(c4212.5,1562.5) 4212.5,1606.25 5231.25,1606.25 cw(c5231.25,1575) 5262.5,1575 5262.5,62.5 cw(c5218.75,62.5) 5218.75,18.75
6Vout on Top Layer "Top Layer-No Net 1" (solid, remove dead copper, pour order 2): 4600,809.79 cw(c4621.46,809.79) 4621.46,831.25 5237.5,831.25 cw(c5237.5,812.5) 5256.25,812.5 5256.25,37.5 cw(c5237.5,37.5) 5237.5,18.75 4625,18.75 cw(c4625,43.75) 4600,43.75
NetC2_1 on Bottom Layer "Bottom Layer-No Net 2" (solid, pour order 36): 3131.25,1400 cw(c3131.25,1425) 3106.25,1425 ccw(c3093.75,1425) 3093.75,1437.5 2418.75,1437.5 cw(c2418.75,1462.5) 2393.75,1462.5 2393.75,1581.25 cw(c2412.5,1581.25) 2412.5,1600 3218.75,1600 cw(c3218.75,1581.25) 3237.5,1581.25 3237.5,1418.75 cw(c3218.75,1418.75) 3218.75,1400
NetC5_2 on Bottom Layer "Bottom Layer-No Net 3" (solid, pour order 34): 2781.25,1368.75 cw(c2800,1368.75) 2800,1387.5 2939.96,1387.5 cw(c2939.96,1362.5) 2964.96,1362.5 2964.96,1002.46 cw(c2943.75,1002.46) 2943.75,981.25 2689.62,981.25 cw(c2689.62,1000) 2670.87,1000 2670.87,1133.37 cw(c2681.25,1133.37) 2681.25,1143.75 2762.5,1143.75 ccw(c2762.5,1162.5) 2781.25,1162.5
NetC5_1 on Bottom Layer "Bottom Layer-No Net 1" (solid, pour order 32): 2406.25,1381.25 2737.5,1381.25 cw(c2737.5,1368.75) 2750,1368.75 2750,1212.5 cw(c2737.5,1212.5) 2737.5,1200 2412.5,1200 cw(c2412.5,1218.75) 2393.75,1218.75 2393.75,1368.75 cw(c2406.25,1368.75)
PGND on Bottom Layer "Bottom Layer-No Net 4" (solid, pour order 20): 1675,18.75 cw(c1675,62.5) 1631.25,62.5 1631.25,881.25 cw(c1668.75,881.25) 1668.75,918.75 3268.75,918.75 cw(c3268.75,887.5) 3300,887.5 3300,556.25 ccw(c3325,556.25) 3325,531.25 3443.75,531.25 cw(c3443.75,506.25) 3468.75,506.25 3468.75,50 cw(c3437.5,50) 3437.5,18.75
GND on Bottom Layer "Bottom Layer-No Net" (solid, remove dead copper, pour order 4): 4268.75,1587.5 cw(c4293.75,1587.5) 4293.75,1612.5 5237.5,1612.5 cw(c5237.5,1587.5) 5262.5,1587.5 5262.5,43.75 cw(c5237.5,43.75) 5237.5,18.75 4306.25,18.75 cw(c4306.25,56.25) 4268.75,56.25

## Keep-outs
Keep-Out Layer:
  text ".Layer_Name" at 577,-858.49 h60

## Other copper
Top Layer:
  text ".Layer_Name" at 577,-858.49 h60
Bottom Layer:
  text ".Layer_Name" at 577,-858.49 h60

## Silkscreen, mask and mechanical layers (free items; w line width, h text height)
Top Overlay:
  text "PMP30280_RevA" at 775,1493.75 h60
  text ".Layer_Name" at 577,-858.49 h40
Bottom Overlay:
  text ".Layer_Name" at 577,-858.49 h35
Top Paste:
  text ".Layer_Name" at 577,-858.49 h60
Bottom Paste:
  text ".Layer_Name" at 577,-858.49 h60
Top Solder:
  text ".Layer_Name" at 577,-858.49 h60
  text ".Layer_Name" at 577,-858.49 h60
Bottom Solder:
  text ".Layer_Name" at 577,-858.49 h60
Drill Guide:
  text ".Layer_Name" at 577,-858.49 h60
M1 Board Outline:
  lines w10: 0,6.25 0,1625 4743.75,1625 5275,1625 5275,6.25 0,6.25
  text ".Layer_Name" at 577,-858.49 h60
M2 Board Dimensions:
  rectangle: 125,-400 500,-275
  rectangle: 0,-275 125,-150
  lines w7: 0,-275 1000,-275 ; 125,-400 125,-150 ; 250,-400 250,-150 ; 500,-400 500,-150 ; 750,-400 750,-150 ; 0,-400 0,-150 1000,-150 1000,-400 0,-400
  text ".Layer_Name" at 577,-858.49 h60
M3 3D STEP Top:
  text ".Layer_Name" at 577,-858.49 h60
M4 3D STEP Bottom:
  text ".Layer_Name" at 577,-858.49 h60
M5 Assembly Top:
  lines w10: -292,-930.17 6308,-930.17 ; -292,-726.83 6310,-726.83 ; -292,-523.5 -292,-1133.5 3713,-1133.5 6310,-1133.5 6310,-523.5 -291.5,-523.5 -291.5,-1133.5 1284,-1133.5 ; 2173,-1133.5 2173,-523.5 ; 3440,-726.83 3440,-523.5 ; 4280,-726.83 4280,-523.5 ; 4902,-1140 4902,-937.17
  text "PCB VIEWED FROM TOP SIDE" at -228.5,-655.67 h60
  text "BOARD #:" at 2248,-655.67 h60
  text ".PRJ_Number" at 2793.5,-655.67 h60
  text "REV:" at 3638,-655.67 h60
  text ".PCB_Rev" at 3929.5,-655.67 h60
  text "SVN REV:" at 4476,-655.67 h60
  text ".VersionControl_RevNumber" at 4982,-655.67 h60
  text "TID #:" at 2248,-859 h60
  text ".TID" at 2793.5,-859 h60
  text "PLOT NAME =" at -228.5,-1064.34 h60
  text ".plot_File_Name" at 577,-1064.34 h60
  text "GENERATED    :" at 2250,-1064.34 h60
  text ".Print_Date" at 3119.5,-1064.34 h60
  text ".Print_Time" at 3848.5,-1064.34 h60
  text "TEXAS INSTRUMENTS" at 5113,-1064.34 h60
M6 Assembly Bottom:
  lines w10: -292.5,-727.33 6309.5,-727.33 ; -290.5,-930.67 6309.5,-930.67 ; 1115.5,-1140.5 1115.5,-937.67 ; 1737.5,-727.33 1737.5,-524 ; 2577.5,-727.33 2577.5,-524 ; 3844.5,-1134 3844.5,-524 ; 4733.5,-1134 6309,-1134 6309,-524 -292.5,-524 -292.5,-1134 2304.5,-1134 6309.5,-1134 6309.5,-524
  text ".VersionControl_RevNumber" at 1035.5,-656.17 h60
  text "SVN REV:" at 1541.5,-656.17 h60
  text ".PCB_Rev" at 2088,-656.17 h60
  text "REV:" at 2379.5,-656.17 h60
  text ".PRJ_Number" at 3224,-656.17 h60
  text "BOARD #:" at 3769.5,-656.17 h60
  text "PCB VIEWED FROM BOTTOM SIDE" at 6246,-656.17 h60
  text ".TID" at 3224,-859.5 h60
  text "TID #:" at 3769.5,-859.5 h60
  text "TEXAS INSTRUMENTS" at 904.5,-1064.84 h60
  text ".Print_Time" at 2169,-1064.84 h60
  text ".Print_Date" at 2898,-1064.84 h60
  text "GENERATED    :" at 3767.5,-1064.84 h60
  text ".plot_File_Name" at 5440.5,-1064.84 h60
  text "PLOT NAME =" at 6246,-1064.84 h60
M9 Title Sheet:
  drawing of 55 lines, arcs and shapes, not listed
  text "1" at 739.84,8036.5 h70
  text "2" at 3235.5,8036.5 h70
  text "3" at 5724.84,8036.5 h70
  text "4" at 8231.51,8036.5 h70
  text "5" at 10730.5,8036.5 h70
  text "6" at 13235.5,8036.5 h70
  text "A" at -416.5,6893.5 h70
  text "A" at 14383.5,6893.5 h70
  text "B" at -416.5,4513.5 h70
  text "B" at 14383.5,4513.5 h70
  text "C" at -416.5,2138.5 h70
  text "C" at 14383.5,2138.5 h70
  text "PROJECT TITLE:" at 11343.5,277.5 h45
  text ".PRJ_Title" at 11393.5,144.17 h70
  text "DESIGNED FOR:" at 11343.5,-23.5 h45
  text ".PRJ_Customer" at 11393.5,-163.5 h70
  text "D" at -416.5,-231.5 h70
  text "D" at 14383.5,-231.5 h70
  text "FILE NAME:" at 11343.5,-323.5 h45
  text ".PCB_File_Name_No_Path" at 11393.5,-443.5 h70
  text "Texas Instruments (TI) and/or its licensors do not warrant the accuracy or completeness of this specification" at 6374,-605.34 h45
  text "ENGINEER:" at 11343.5,-613.5 h45
  text "LAYOUT BY:" at 12848.5,-613.5 h45
  text "or any information contained therein. TI and/or its licensors do not warrant that this design will meet" at 6329.01,-718 h45
  text ".PRJ_Engineer" at 11393.5,-768.49 h70
  text ".PCB_Layout" at 12899,-768.49 h70
  text "the specifications, will be suitable for your application or fit for any particular purpose, or will operate in" at 6329.01,-830.67 h45
  text ".Layer_Name" at 577,-858.49 h60
  text "ALTIUM DESIGNER VERSION:" at 12848.5,-923.5 h45
  text "an implementation. TI and/or its licensors do not warrant that the design is production worthy. You should" at 6329.01,-943.33 h45
  text "completely validate and test your design implementation to confirm the system functionality for your application." at 6374,-1056 h45
  text ".print_Scale" at 11393.5,-1056.83 h70
  text ".Application_BuildNumber" at 12899,-1056.83 h70
  text "1" at 739.84,-1263.5 h70
  text "2" at 3235.5,-1263.5 h70
  text "3" at 5724.84,-1263.5 h70
  text "4" at 8231.51,-1263.5 h70
  text "5" at 10730.5,-1263.5 h70
  text "6" at 13235.5,-1263.5 h70
M10 Fab Notes:
  text ".Layer_Name" at 577,-858.49 h60
M11 Gerber Information:
  lines w10: -292,-930.17 6308,-930.17 ; -292,-726.83 6310,-726.83 ; -292,-523.5 -292,-1133.5 3713,-1133.5 6310,-1133.5 6310,-523.5 -291.5,-523.5 -291.5,-1133.5 1284,-1133.5 ; 2173,-1133.5 2173,-523.5 ; 3440,-726.83 3440,-523.5 ; 4280,-726.83 4280,-523.5 ; 4902,-1140 4902,-937.17
  text "ALL ARTWORK VIEWED FROM TOP SIDE" at -228.5,-655.67 h60
  text "BOARD #:" at 2248,-655.67 h60
  text ".PRJ_Number" at 2793.5,-655.67 h60
  text "REV:" at 3638,-655.67 h60
  text ".PCB_Rev" at 3929.5,-655.67 h60
  text "SVN REV:" at 4476,-655.67 h60
  text ".VersionControl_RevNumber" at 4982,-655.67 h60
  text "LAYER NAME =" at -228.5,-858.49 h60
  text "TID #:" at 2248,-859 h60
  text ".TID" at 2793.5,-859 h60
  text "PLOT NAME =" at -228.5,-1064.34 h60
  text ".plot_File_Name" at 577,-1064.34 h60
  text "GENERATED    :" at 2250,-1064.34 h60
  text ".Print_Date" at 3119.5,-1064.34 h60
  text ".Print_Time" at 3848.5,-1064.34 h60
  text "TEXAS INSTRUMENTS" at 5113,-1064.34 h60
M12 Stackup:
  text ".Layer_Name" at 577,-858.49 h60
M13 Component Bodies Top:
  text ".Layer_Name" at 577,-858.49 h60
M14 Component Bodies Bottom:
  text ".Layer_Name" at 577,-858.49 h60
M15 Courtyards Top:
  text ".Layer_Name" at 577,-858.49 h60
M16 Courtyards Bottom:
  text ".Layer_Name" at 577,-858.49 h60
Drill Drawing:
  text ".Layer_Name" at 577,-858.49 h60

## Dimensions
0,0 to 5275,6.25 on M2 Board Dimensions
0,0 to 0,1625 on M2 Board Dimensions
0,-400 to 1000,-400 on M2 Board Dimensions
